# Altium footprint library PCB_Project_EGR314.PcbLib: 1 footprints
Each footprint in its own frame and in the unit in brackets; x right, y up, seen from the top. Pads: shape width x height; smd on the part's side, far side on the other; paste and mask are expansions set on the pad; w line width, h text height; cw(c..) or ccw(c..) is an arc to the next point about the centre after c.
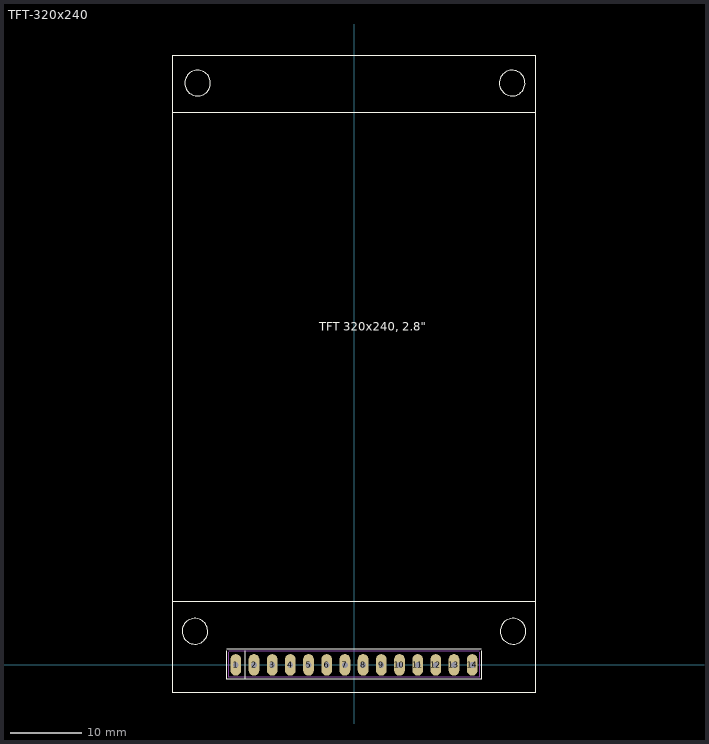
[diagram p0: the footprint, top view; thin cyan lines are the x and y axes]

## TFT-320x240 [mm]
pads (14):
  rrect100% 1.5x3 hole 0.8: 1(-16.51,0) 2(-13.97,0) 3(-11.43,0) 4(-8.89,0) 5(-6.35,0) 6(-3.81,0) 7(-1.27,0) 8(1.27,0) 9(3.81,0) 10(6.35,0) 11(8.89,0) 12(11.43,0) 13(13.97,0) 14(16.51,0)
F.SilkS:
  circle w0.12: c-21.844,81.28 r1.796
  circle w0.12: c-22.225,4.699 r1.796
  circle w0.12: c22.098,81.28 r1.796
  circle w0.12: c22.225,4.699 r1.796
  lines w0.12: -25.4,8.89 25.4,8.89 ; -25.4,77.216 25.4,77.216 ; -17.76,2 -17.76,-2 17.76,-2 17.76,2 ; -17.76,2.254 17.76,2.254 ; -15.24,-2 -15.24,2 ; -25.4,-3.81 -25.4,85.09 25.4,85.09 25.4,-3.81 -25.4,-3.81
  text "TFT 320x240, 2.8\"" at -4.832,46.288 h2
F.CrtYd:
  lines w0.05: -17.51,1.75 -17.51,-1.75 17.51,-1.75 17.51,1.75 ; -17.51,2.004 17.51,2.004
